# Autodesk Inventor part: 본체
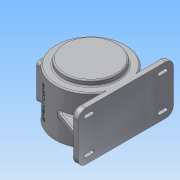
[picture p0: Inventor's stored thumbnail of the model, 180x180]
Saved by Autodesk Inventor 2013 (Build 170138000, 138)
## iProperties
Created: 2015-06
Part Number: 본체
Material: 알루미늄 6061
Document SubType Name: Modeling
Designer: Administrator
Density: 2.71 g/cm^3
Mass: 3338.13 g
Surface Area: 2328.16 cm^2
Volume: 1231.78 cm^3
Author: Administrator
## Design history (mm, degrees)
sketch "스케치2"
  geometry: C1 r 85 at (0, 0); 1 further point
  constraints: 1 centre point, 1 coincident
  dimensions: "d6" = 170 diameter of C1
extrude "돌출2" new body sketch "스케치2" distance "d7" = 118; taper "d8" = 0 deg
sketch "스케치3"
  geometry: C1 r 85 at (0, 0) reference; C2 r 65 at (0, 0)
  constraints: 1 centre point, 1 coincident
  dimensions: "d9" = 130 diameter of C2
extrude "돌출3" join sketch "스케치3" distance "d10" = 13; taper "d11" = 0 deg
sketch "스케치4"
  geometry: C1 r 85 at (0, 0) reference; C2 r 65 at (0, 0)
  constraints: 1 centre point, 1 coincident
  dimensions: "d12" = 130 diameter of C2
extrude "돌출4" join sketch "스케치4" distance "d13" = 3; taper "d14" = 0 deg
sketch "스케치8"
  geometry: L1 (-85, 0)-(-85, 118) reference; L2 (-85, 118)-(-65, 118) reference; L3 (-65, 118)-(-65, 131) reference; L4 (-65, 131)-(65, 131) reference; L5 (65, 131)-(65, 118) reference; L6 (65, 118)-(85, 118) reference; L7 (85, 118)-(85, 0) reference; L8 (85, 0)-(65, 0) reference; L9 (65, 0)-(65, -3) reference; L10 (65, -3)-(-65, -3) reference; L11 (-65, -3)-(-65, 0) reference; L12 (-65, 0)-(-85, 0) reference; L13 (15, 123.5)-(15, 120.5); L14 (15, 120.5)-(23.5, 120.5); L15 (23.5, 120.5)-(23.5, 106.5); L16 (23.5, 106.5)-(29.368, 106.5); L17 (29.368, 106.5)-(31, 110); L18 (31, 110)-(77, 110); L19 (77, 110)-(77, 8); L20 (77, 8)-(47.5, 8); L21 (47.5, 8)-(47.5, -3); L22 (15, 123.5)-(0, 123.5); L23 (0, 123.5)-(0, -3); L24 (47.5, -3)-(0, -3); 1 further point
  constraints: 24 end point, 2 perpendicular, 1 collinear, 1 midpoint, 1 point on line
  dimensions: "d64" = 3 distance between parallel lines of L14 L22; "d65" = 14 distance between parallel lines of L16 L14; "d66" = 3.5 distance between parallel lines of L16 L18; "d67" = 115 deg angle of L16 L17; "d68" = 102 distance between parallel lines of L18 L20; "d70" = 7.5 distance between parallel lines of L22 L4; "d71" = 154 diameter of L19 L23; "d72" = 47 diameter of L15 L23; "d73" = 30 diameter of L13 L23; "d74" = 62 diameter of L17.end L23; "d75" = 95 diameter of L21 L23
  node "절단 모서리 투영2"
revolve "회전1" stored, may be unused: angle "d76" = 90 deg
node "작업 평면2"
sketch "스케치9"
  geometry: L1 (-97, 118)-(97, 118); L2 (115, 100)-(115, 18); L3 (97, 0)-(-97, 0); L4 (-115, 18)-(-115, 100); L5 (0, 0)-(0, 118) reference; A1 r 18 centre (-97, 100) between (-97, 118) and (-115, 100); A2 r 18 centre (-97, 18) between (-115, 18) and (-97, 0); A3 r 18 centre (97, 18) between (97, 0) and (115, 18); A4 r 18 centre (97, 100) between (115, 100) and (97, 118); 6 further points
  constraints: 8 end point, 8 point on circle, 8 tangent, 6 point on line, 4 centre point, 3 equal radius, 3 midpoint, 2 parallel, 1 coincident, 1 horizontal, 1 horizontal alignment, 1 perpendicular
  dimensions: "d78" = 230 distance of point (-115, 118) point (115, 118); "d80" = 118 distance of point (-115, 0) point (-115, 118); "d81" = 18 radius of A1
extrude "돌출6" join sketch "스케치9" distance "d82" = 14; taper "d83" = 0 deg
sketch "스케치10"
  geometry: L1 (118, 46.733)-(118, 97) reference; L2 (0, 97)-(0, 46.733) reference; L3 (91, 97)-(91, 81); L4 (109, 81)-(109, 97); L5 (18, 115)-(100, 115) reference; L6 (118, 97)-(118, 46.733) reference; L7 (0, 46.733)-(118, 46.733) reference; L8 (0, -46.733)-(0, 46.733) reference; L9 (118, -46.733)-(0, -46.733) reference; L10 (118, -46.733)-(118, -97) reference; L11 (100, -115)-(18, -115) reference; L12 (0, -97)-(0, -46.733) reference; L13 (0, 46.733)-(0, 97) reference; L14 (118, 46.733)-(118, -46.733) reference; L15 (8, 29.799)-(8, -29.799) reference; L16 (8, -29.799)-(110, -29.799) reference; L17 (110, -29.799)-(110, 29.799) reference; L18 (110, 29.799)-(8, 29.799) reference; L19 (96, 97)-(96, 81); L20 (104, 81)-(104, 97); A1 r 18 centre (100, 97) between (118, 97) and (100, 115) reference; A2 r 9 centre (100, 81) between (91, 81) and (109, 81); A3 r 9 centre (100, 97) between (109, 97) and (91, 97); A4 r 18 centre (18, 97) between (18, 115) and (0, 97) reference; A5 r 18 centre (100, 97) between (118, 97) and (100, 115) reference; A6 r 18 centre (100, -97) between (100, -115) and (118, -97) reference; A7 r 18 centre (18, -97) between (0, -97) and (18, -115) reference; A8 r 4 centre (100, 81) between (96, 81) and (104, 81); A9 r 4 centre (100, 97) between (104, 97) and (96, 97); 1 further point
  constraints: 8 end point, 8 point on circle, 4 centre point, 3 tangent, 2 parallel, 1 coincident, 1 equal radius, 3 other
  dimensions: "d84" = 18 distance between parallel lines of L4 L3; "d86" = 16 distance of A2.centre A1.centre; "d87" = 8 distance between parallel lines of L20 L19
  node "절단 모서리 투영4"
extrude "돌출7" join sketch "스케치10" distance "d88" = 3; taper "d89" = 0 deg
extrude "돌출8" cut sketch "스케치10" distance "d90" = 3; taper "d92" = 0 deg; dims "d91" = 14, "d93" = 0
node "작업 평면3"
sketch "스케치11"
  geometry: L1 (71, -29.799)-(71, 29.799) reference; L2 (71, 46.733)-(71, 115) reference; L3 (71, 115)-(85, 115) reference; L4 (85, 115)-(85, -115) reference; L5 (85, -115)-(71, -115) reference; L6 (71, -115)-(71, -46.733) reference; L7 (71, -109)-(4.703, -84.87); L8 (71, 109)-(4.703, 84.87); A1 r 77 centre (0, 0) between (71, 29.799) and (71, -29.799) reference; A2 r 85 centre (0, 0) between (71, 46.733) and (71, -46.733) reference; 1 further point
  constraints: 4 end point, 2 point on circle, 2 point on line
  dimensions: "d101" = 6 distance of L7.start L5.end; "d102" = 110 deg angle of L7 L6; "d103" = 6 distance of L2.end L8.start; "d104" = 110 deg angle of L2 L8
  node "절단 모서리 투영5"
feature "리브1" dims "d105" = 1, "d106" = 15, "d107" = 0, "d108" = 0, "d109" = 1, "d110" = 1
feature "리브2" dims "d111" = 1, "d112" = 15, "d113" = 0, "d114" = 0, "d115" = 1, "d116" = 1
node "작업 평면4"
sketch "스케치12"
  geometry: L1 (-35.5, 101.5)-(35.5, 101.5); L2 (42.5, 94.5)-(42.5, 23.5); L3 (35.5, 16.5)-(-35.5, 16.5); L4 (-42.5, 23.5)-(-42.5, 94.5); L5 (115, 18)-(115, 100) reference; A1 r 7 centre (-35.5, 94.5) between (-35.5, 101.5) and (-42.5, 94.5); A2 r 7 centre (-35.5, 23.5) between (-42.5, 23.5) and (-35.5, 16.5); A3 r 7 centre (35.5, 23.5) between (35.5, 16.5) and (42.5, 23.5); A4 r 7 centre (35.5, 94.5) between (42.5, 94.5) and (35.5, 101.5); 8 further points
  constraints: 8 end point, 8 point on circle, 8 point on line, 8 tangent, 4 centre point, 3 equal radius, 3 midpoint, 2 parallel, 1 horizontal, 1 horizontal alignment, 1 perpendicular, 1 vertical alignment
  dimensions: "d118" = 85 distance between parallel lines of L2 L4; "d120" = 85 distance between parallel lines of L1 L3; "d127" = 7 radius of A1
extrude "돌출9" join sketch "스케치12" stored distance "d121" = 3; taper "d122" = 0 deg
sketch "스케치13"
  geometry: L1 (101.5, 35.5)-(101.5, -35.5) reference; L2 (23.5, 42.5)-(94.5, 42.5) reference; C1 r 35 at (59, 0); 6 further points
  constraints: 2 midpoint, 1 centre point, 1 horizontal alignment, 1 vertical alignment
  dimensions: "d123" = 70 diameter of C1
extrude "돌출10" cut sketch "스케치13" stored distance "d124" = 3; taper "d125" = 0 deg
fillet "모깎기1" dims "d126" = 3
fillet "모깎기2" dims "d128" = 3
fillet "모깎기3" dims "d129" = 3
chamfer "모따기1" distance "d130" = 1; stored, may be unused: second distance "d131" = 2, angle "d132" = 45 deg
fillet "모깎기4" dims "d133" = 3
fillet "모깎기5" dims "d134" = 0.3
fillet "모깎기6" dims "d135" = 3
hole "구멍2" diameter "d138" = 3.242; stored, may be unused: countersink angle "d142" = 90 deg, drill point angle "d144" = 118 deg; dims "d136" = 10, "d137" = 10, "d139" = 10, "d140" = 4, "d141" = 2, "d143" = 13
sketch "스케치14"
  geometry: C1 r 47.5 at (0, 0) reference; C2 r 65 at (0, 0) reference; C3 r 47.5 at (0, 0) reference; 1 further point
  constraints: 1 vertical alignment
  dimensions: "d152" = 55 distance of C1.centre point (0, 55)
hole "구멍3" sketch "스케치14" at (0, 55) diameter "d153" = 3.242; stored, may be unused: countersink angle "d157" = 90 deg, drill point angle "d159" = 0 deg; dims "d154" = 10, "d155" = 4, "d156" = 2, "d158" = 13
node "작업축1"
node "작업 평면6"
  node "작업 평면5"
node "작업축2"
  node "작업 평면7"
sketch "스케치15"
  geometry: L1 (101.243, -88.5)-(101.243, -6.5) reference; L2 (-16.09, 51.3)-(-16.09, -136.3) reference; 3 further points
  constraints: 1 horizontal alignment, 1 midpoint, 1 point on line, 1 other
feature "엠보싱1" sketch "스케치15" dims "d166" = 0.5, "d167" = 0
fillet "모깎기7" dims "d168" = 3
fillet "모깎기8" dims "d169" = 3
revolve "회전2" stored, may be unused: angle "d170" = 90 deg
fillet "모깎기9" dims "d171" = 3
fillet "모깎기10" dims "d172" = 0.3
fillet "모깎기11" dims "d173" = 3
chamfer "모따기2" distance "d174" = 1; stored, may be unused: second distance "d175" = 2, angle "d176" = 45 deg
node "솔리드2"
pattern_linear "직사각형 패턴1" dims "d96" = 82, "d99" = 178
pattern_linear "직사각형 패턴2" dims "d147" = 71, "d150" = 71
pattern_circular "원형 패턴1" dims angle "d161" = 360 deg
node "절단 모서리 투영3"
node "절단 모서리 투영6"
other parameters: "d77" = 85, "d100" = 59, "d117" = -173, "d163" = 75 deg, "d164" = -91.25, "d165" = -25 deg
